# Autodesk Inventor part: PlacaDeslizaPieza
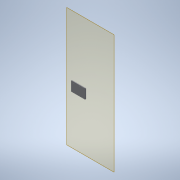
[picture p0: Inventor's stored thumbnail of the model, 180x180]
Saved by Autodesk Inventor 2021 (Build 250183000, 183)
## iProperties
Created: 2021-02
Part Number: PlacaDeslizaPieza
Material: Genérico
Document SubType Name: Modeling
Designer: ATOUZA
Density: 1 g/cm^3
Appearance: Valor por defecto
Author: ATOUZA
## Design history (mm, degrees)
node "Plano de trabajo1"
sketch "Boceto1"
  geometry: L1 (16.874, 260.305)-(-25.126, 260.305) reference; L2 (-25.126, 192.305)-(16.874, 192.305) reference; L3 (-67.126, 243.805)-(-67.126, 208.805) reference; L4 (16.874, 260.305)-(-83.126, 260.305); L5 (-83.126, 260.305)-(-83.126, 192.305); L6 (-83.126, 192.305)-(16.874, 192.305); L7 (16.874, 192.305)-(16.874, 260.305); C1 r 2 at (0.374, 256.199) reference; C2 r 2 at (-19.626, 256.199) reference; C3 r 2 at (-19.626, 196.305) reference; C4 r 2 at (0.374, 196.305) reference; C5 r 2 at (0.374, 256.199); C6 r 2 at (-19.626, 256.199); C7 r 2 at (0.374, 196.305); C8 r 2 at (-19.626, 196.305); C9 r 2 at (-59.626, 252.555) reference; C10 r 2 at (-59.626, 200.055) reference; C11 r 2 at (-59.626, 252.555); C12 r 2 at (-59.626, 200.055); 1 further point
  constraints: 8 end point, 6 centre point, 6 coincident, 6 concentric, 2 parallel, 1 horizontal, 1 perpendicular
  dimensions: "d0" = 100 distance of L6.end L5.end
extrude "Extrusión1" new body sketch "Boceto1" distance "d1" = 5; taper "d2" = 0 deg
fillet "Empalme1" dims "d3" = 4
node "Sólido1"
node "Referencia1"
node "Referencia2"
node "Referencia3"
node "Referencia4"
node "Referencia5"
node "Referencia6"
node "Referencia7"
node "Referencia8"
node "Referencia9"
